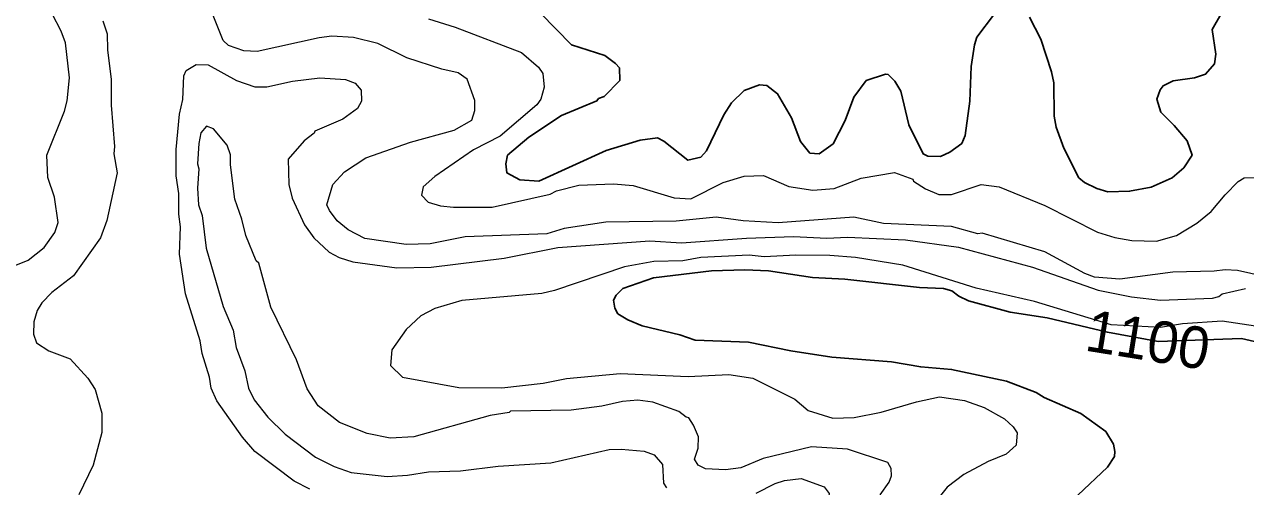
# Model space of a CAD drawing. Extents: x 447.8 to 473.9, y 7733.1 to 7760.8.
# Drawn here: x 467.383 to 469.73, y 7738.255 to 7739.144 of the extents above; entities that cross this region are included whole.
import ezdxf
from ezdxf.enums import TextEntityAlignment as Align

# ---------------------------------------------------------------- set-up
doc = ezdxf.new("R2010")
doc.units = 0
doc.header["$LTSCALE"] = 0.032
doc.layers.add('1', color=7, linetype='Continuous', lineweight=25)
doc.layers.add('2', color=7, linetype='Continuous', lineweight=13)
doc.layers.add('61', color=7, linetype='Continuous')

msp = doc.modelspace()

# ---------------------------------------------------------------- linework, layer by layer
at = {"layer": '1'}
for points in [[(468.3746, 7739.1656), (468.4344, 7739.1042), (468.4986, 7739.0843), (468.5192, 7739.0687), (468.5263, 7739.06), (468.5273, 7739.036), (468.4969, 7739.0051), (468.4865, 7739.0013), (468.4831, 7738.9969), (468.4154, 7738.9689), (468.3525, 7738.927), (468.3111, 7738.8924), (468.3079, 7738.8757), (468.3101, 7738.8585), (468.3348, 7738.8448), (468.3715, 7738.8424), (468.5011, 7738.9016), (468.566, 7738.9212), (468.5993, 7738.9256), (468.6119, 7738.9196), (468.6577, 7738.8827), (468.683, 7738.8888), (468.6936, 7738.9009), (468.727, 7738.9702), (468.7418, 7738.9932), (468.7663, 7739.0168), (468.7956, 7739.0274), (468.8097, 7739.0265), (468.8305, 7739.0106), (468.8569, 7738.9643), (468.8743, 7738.9185), (468.8925, 7738.8961), (468.9102, 7738.8953), (468.9372, 7738.9143), (468.9602, 7738.959), (468.9771, 7739.0039), (469.0009, 7739.036), (469.038, 7739.0483), (469.0427, 7739.0476), (469.0557, 7739.0346), (469.067, 7739.0154), (469.0825, 7738.9505), (469.1101, 7738.8947), (469.1189, 7738.8907), (469.1438, 7738.8899), (469.1612, 7738.8983), (469.1843, 7738.9149), (469.1911, 7738.9301), (469.1999, 7738.9962), (469.2023, 7739.0627), (469.2087, 7739.1044), (469.2135, 7739.1193), (469.2474, 7739.1644)], [(469.3148, 7739.1578), (469.3362, 7739.1152), (469.357, 7739.0527), (469.3611, 7739.0314), (469.3619, 7738.9677), (469.366, 7738.9462), (469.3808, 7738.906), (469.4091, 7738.849), (469.4203, 7738.84), (469.4437, 7738.8282), (469.4654, 7738.8223), (469.507, 7738.823), (469.5484, 7738.8309), (469.5887, 7738.8492), (469.6112, 7738.868), (469.6272, 7738.8923), (469.6174, 7738.9203), (469.5928, 7738.9497), (469.5668, 7738.9753), (469.5593, 7738.9999), (469.5654, 7739.0183), (469.5712, 7739.0258), (469.5905, 7739.0354), (469.6318, 7739.041), (469.6529, 7739.0483), (469.6704, 7739.0682), (469.6729, 7739.0863), (469.6658, 7739.134), (469.6853, 7739.1686)], [(469.4073, 7738.2392), (469.4642, 7738.2928), (469.4777, 7738.3134), (469.4789, 7738.3232), (469.4758, 7738.3373), (469.4611, 7738.3615), (469.413, 7738.396), (469.3426, 7738.4267), (469.3272, 7738.436), (469.2701, 7738.4582), (469.1648, 7738.4806), (469.1055, 7738.4856), (469.0492, 7738.4952), (468.9349, 7738.5042), (468.8559, 7738.5161), (468.7746, 7738.533), (468.6718, 7738.5369), (468.6426, 7738.5474), (468.5701, 7738.5644), (468.5426, 7738.5758), (468.5234, 7738.5876), (468.5179, 7738.5987), (468.5152, 7738.6139), (468.5204, 7738.6234), (468.5332, 7738.6362), (468.592, 7738.6564), (468.7031, 7738.6699), (468.7677, 7738.6723), (468.8129, 7738.6699), (468.8973, 7738.6573), (468.9596, 7738.6539), (469.103, 7738.6378), (469.1495, 7738.6362), (469.1655, 7738.6314), (469.179, 7738.6212), (469.1973, 7738.6124), (469.2775, 7738.591), (469.3483, 7738.5801), (469.4643, 7738.552), (469.562, 7738.5346), (469.7223, 7738.54), (469.8086, 7738.5203)]]:
    msp.add_lwpolyline(points, dxfattribs=at)
at = {"layer": '2'}
for points in [[(467.3053, 7738.6569), (467.3903, 7738.6904), (467.4208, 7738.7152), (467.4416, 7738.7436), (467.4477, 7738.7631), (467.4406, 7738.8118), (467.4279, 7738.8497), (467.4262, 7738.8927), (467.4599, 7738.9772), (467.4647, 7738.9969), (467.4694, 7739.0414), (467.4615, 7739.1081), (467.4533, 7739.1311), (467.4361, 7739.1639)], [(467.5334, 7739.1508), (467.5416, 7739.1257), (467.5423, 7739.0951), (467.5496, 7739.0382), (467.5498, 7738.9887), (467.556, 7738.9092), (467.5545, 7738.895), (467.5608, 7738.8583), (467.5415, 7738.7666), (467.5289, 7738.7335), (467.4769, 7738.6606), (467.4356, 7738.6287), (467.4161, 7738.6084), (467.4071, 7738.5939), (467.4007, 7738.572), (467.4006, 7738.5486), (467.4059, 7738.5318), (467.43, 7738.5165), (467.4707, 7738.501), (467.5049, 7738.4637), (467.519, 7738.4418), (467.5319, 7738.3966), (467.5319, 7738.3592), (467.5147, 7738.2967), (467.4872, 7738.2398)], [(468.0374, 7738.732), (468.0049, 7738.749), (467.984, 7738.7663), (467.9689, 7738.7862), (467.9641, 7738.797), (467.9754, 7738.8358), (467.9983, 7738.8607), (468.0388, 7738.8872), (468.1246, 7738.9177), (468.2085, 7738.9408), (468.2429, 7738.9597), (468.2485, 7738.9782), (468.2485, 7738.9978), (468.2341, 7739.0384), (468.2164, 7739.0506), (468.1851, 7739.0577), (468.1178, 7739.0793), (468.0622, 7739.1073), (468.0154, 7739.1189), (467.9739, 7739.1213), (467.9492, 7739.1181), (467.8304, 7739.0916), (467.8046, 7739.0933), (467.7748, 7739.103), (467.7649, 7739.1131), (467.7453, 7739.161)], [(468.1595, 7739.1547), (468.2108, 7739.1386), (468.3383, 7739.0899), (468.3712, 7739.0619), (468.379, 7739.0494), (468.3816, 7739.0231), (468.3755, 7739.0001), (468.368, 7738.989), (468.297, 7738.929), (468.246, 7738.9028), (468.1715, 7738.8516), (468.1491, 7738.8314), (468.1462, 7738.8158), (468.1589, 7738.8023), (468.1825, 7738.7951), (468.2078, 7738.7926), (468.2818, 7738.7926), (468.3931, 7738.8176), (468.4052, 7738.8242), (468.4483, 7738.8349), (468.515, 7738.8375), (468.5529, 7738.8343), (468.6314, 7738.8103), (468.6634, 7738.8087), (468.726, 7738.8397), (468.766, 7738.8521), (468.8033, 7738.8535), (468.852, 7738.8325), (468.8981, 7738.8249), (468.9392, 7738.8286), (468.9912, 7738.848), (469.055, 7738.8592), (469.0901, 7738.8461), (469.0919, 7738.8424), (469.1146, 7738.8277), (469.1406, 7738.8166), (469.1649, 7738.8167), (469.2217, 7738.8358), (469.2566, 7738.8319), (469.3438, 7738.7957), (469.4452, 7738.7442), (469.4786, 7738.734), (469.5115, 7738.7285), (469.5587, 7738.7269), (469.5971, 7738.7382), (469.6364, 7738.7617), (469.6638, 7738.7842), (469.6904, 7738.8164), (469.7157, 7738.8417), (469.7274, 7738.8491), (469.7522, 7738.8495)], [(467.6891, 7739.0451), (467.6938, 7739.0554), (467.7132, 7739.0667), (467.7361, 7739.0658), (467.7906, 7739.0359), (467.8254, 7739.0235), (467.849, 7739.0236), (467.8984, 7739.0345), (467.9508, 7739.041), (468.0001, 7739.0378), (468.0184, 7739.0306), (468.0298, 7739.0172), (468.0306, 7738.996), (468.0228, 7738.9822), (467.9947, 7738.9614), (467.941, 7738.9384), (467.9398, 7738.9347), (467.9202, 7738.9203), (467.8898, 7738.885), (467.891, 7738.8362), (467.8977, 7738.8095), (467.9209, 7738.7586), (467.9389, 7738.7334), (467.9683, 7738.7059), (467.9878, 7738.6959), (468.0138, 7738.6877), (468.0988, 7738.6756), (468.1643, 7738.6772), (468.3052, 7738.6946), (468.408, 7738.7149), (468.5849, 7738.7276), (468.6457, 7738.7237), (468.7709, 7738.7332), (468.8607, 7738.7364), (468.9251, 7738.7332), (468.9648, 7738.7348), (469.0765, 7738.73), (469.1784, 7738.7156), (469.3202, 7738.6769), (469.4466, 7738.6327), (469.5106, 7738.6202), (469.5661, 7738.6139), (469.6662, 7738.6179), (469.6786, 7738.6211), (469.6849, 7738.626), (469.7299, 7738.6362)], [(467.6794, 7738.8189), (467.6748, 7738.8525), (467.6746, 7738.9035), (467.6811, 7738.971), (467.6874, 7738.9994), (467.6891, 7739.0451)], [(469.0273, 7738.2398), (469.0448, 7738.2642), (469.0492, 7738.276), (469.0486, 7738.2903), (469.0422, 7738.3018), (468.9648, 7738.3274), (468.8959, 7738.3316), (468.8024, 7738.3097), (468.7597, 7738.2917), (468.7302, 7738.2876), (468.6921, 7738.2898), (468.6776, 7738.2965), (468.6704, 7738.3082), (468.6775, 7738.3296), (468.6783, 7738.351), (468.669, 7738.3735), (468.6598, 7738.3875), (468.6546, 7738.3886), (468.6405, 7738.3998), (468.5907, 7738.418), (468.5619, 7738.4214), (468.5323, 7738.419), (468.4928, 7738.41), (468.4334, 7738.4021), (468.3171, 7738.4006), (468.3148, 7738.398), (468.2781, 7738.392), (468.1312, 7738.3509), (468.0859, 7738.3486), (468.0414, 7738.3574), (467.9881, 7738.3784), (467.9477, 7738.4105), (467.9264, 7738.4431), (467.9057, 7738.4989), (467.8565, 7738.6005), (467.8333, 7738.6848), (467.8281, 7738.6892), (467.8082, 7738.738), (467.801, 7738.7696), (467.7874, 7738.8081), (467.7789, 7738.8737), (467.7788, 7738.8933), (467.7728, 7738.9118), (467.7463, 7738.943), (467.7325, 7738.9485), (467.7221, 7738.9355), (467.718, 7738.9151), (467.7155, 7738.8761), (467.718, 7738.8665), (467.7156, 7738.829), (467.7172, 7738.7971), (467.7244, 7738.7762), (467.7324, 7738.714), (467.7646, 7738.6016), (467.784, 7738.5558), (467.7901, 7738.5229), (467.8062, 7738.478), (467.8135, 7738.4444), (467.8244, 7738.4225), (467.8504, 7738.3892), (467.8841, 7738.3563), (467.9421, 7738.3118), (467.9779, 7738.2939), (468.011, 7738.2828), (468.0798, 7738.2748), (468.1194, 7738.2772), (468.1592, 7738.2836), (468.2211, 7738.2855), (468.2931, 7738.2948), (468.3944, 7738.3012), (468.5067, 7738.3268), (468.5295, 7738.3276), (468.574, 7738.3236), (468.5931, 7738.3163), (468.6093, 7738.2977), (468.611, 7738.2622), (468.6171, 7738.2528)], [(467.9317, 7738.2502), (467.9013, 7738.2656), (467.8258, 7738.323), (467.8021, 7738.3507), (467.7527, 7738.4201), (467.742, 7738.4448), (467.7387, 7738.4655), (467.7242, 7738.5111), (467.7204, 7738.5355), (467.6924, 7738.6258), (467.6811, 7738.7021), (467.6826, 7738.7548), (467.6795, 7738.779), (467.6794, 7738.8189)], [(468.4205, 7738.7518), (468.3868, 7738.7413), (468.2297, 7738.7357), (468.1627, 7738.7221), (468.1168, 7738.7205), (468.0374, 7738.732)], [(469.7913, 7738.6535), (469.7145, 7738.6706), (469.6907, 7738.6722), (469.6697, 7738.6692), (469.5901, 7738.6675), (469.4885, 7738.654), (469.4394, 7738.658), (469.4208, 7738.665), (469.3438, 7738.7067), (469.2234, 7738.7428), (469.2151, 7738.7414), (469.1648, 7738.7556), (469.0337, 7738.7612), (468.9768, 7738.7733), (468.8317, 7738.7622), (468.7644, 7738.766), (468.7126, 7738.7733), (468.6356, 7738.7654), (468.5, 7738.7637), (468.4205, 7738.7518)], [(469.7748, 7738.5601), (469.6847, 7738.5737), (469.6085, 7738.5682), (469.5666, 7738.5614), (469.4716, 7738.5662), (469.324, 7738.6115), (469.2121, 7738.6371), (469.0714, 7738.6811), (468.98, 7738.6958), (468.9306, 7738.6996), (468.8655, 7738.7004), (468.8045, 7738.6972), (468.7757, 7738.7004), (468.6832, 7738.6958), (468.6481, 7738.6892), (468.5923, 7738.6884), (468.5359, 7738.678), (468.4016, 7738.6325), (468.3772, 7738.6267), (468.2233, 7738.6131), (468.1717, 7738.5978), (468.1449, 7738.5834), (468.1165, 7738.5572), (468.0892, 7738.5185), (468.0866, 7738.4882), (468.1093, 7738.4656), (468.2178, 7738.4456), (468.3004, 7738.4454), (468.3797, 7738.4543), (468.4246, 7738.4631), (468.5279, 7738.4727), (468.6587, 7738.4672), (468.7366, 7738.4711), (468.7826, 7738.4638), (468.8636, 7738.4233), (468.8889, 7738.4019), (468.9366, 7738.3872), (468.9777, 7738.3885), (469.0297, 7738.3983), (469.0973, 7738.4184), (469.1415, 7738.4278), (469.1896, 7738.4206), (469.2275, 7738.4073), (469.2663, 7738.3855), (469.2834, 7738.3701), (469.2906, 7738.3586), (469.2889, 7738.335)], [(469.2889, 7738.335), (469.2698, 7738.3178), (469.2352, 7738.3039), (469.1883, 7738.2789), (469.1565, 7738.2545), (469.0956, 7738.1782)], [(468.7894, 7738.243), (468.8257, 7738.2611)], [(468.8257, 7738.2611), (468.8439, 7738.2672), (468.8756, 7738.2708), (468.9197, 7738.2553), (468.9294, 7738.2419), (468.926, 7738.2125)]]:
    msp.add_lwpolyline(points, dxfattribs=at)

# ---------------------------------------------------------------- texts
at = {"layer": '61'}
msp.add_text('1100', height=0.08, rotation=350.796, dxfattribs=at).set_placement((469.536, 7738.4983), align=Align.CENTER)

doc.saveas('drawing.dxf')
